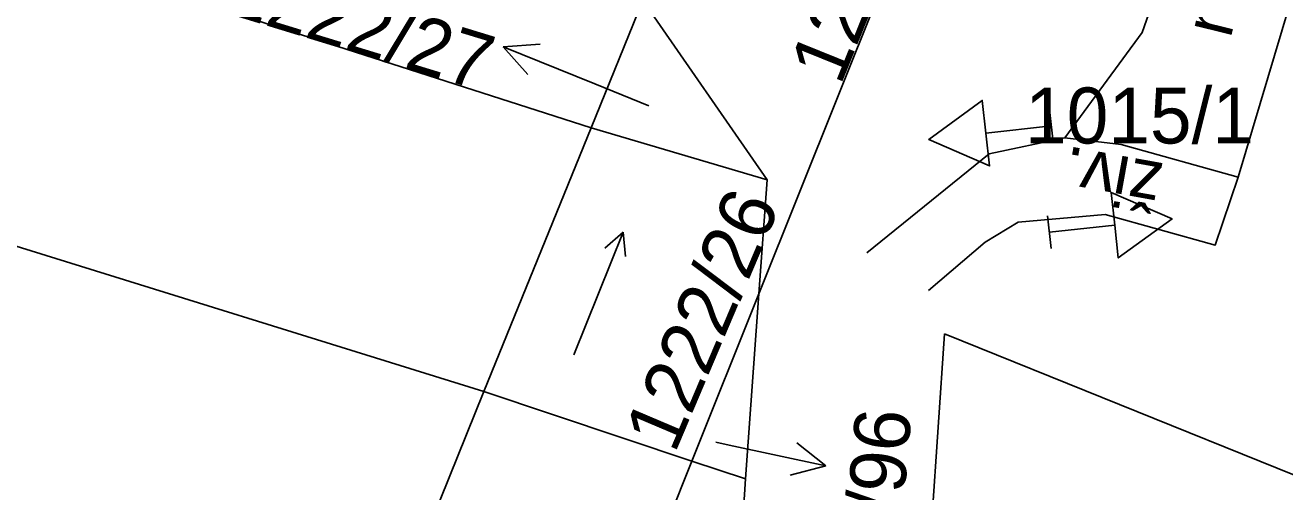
# Model space of a CAD drawing. Extents: x -779302 to -774398, y -1144902 to -1142831.
# Drawn here: x -776127.74 to -776089.47, y -1144254.14 to -1144239.97 of the extents above; entities that cross this region are included whole.
import ezdxf

# ---------------------------------------------------------------- set-up
doc = ezdxf.new("R2010")
doc.units = 0
for name, color, linetype in [('Hranice parcel', 7, 'Continuous'), ('Parcelní čísla', 7, 'Continuous'), ('Pop  PČ popisy', 7, 'Continuous'), ('zjednodus_g_situ-seda - Vrstva 51', 7, 'Continuous'), ('Značky kultur', 7, 'Continuous')]:
    doc.layers.add(name, color=color, linetype=linetype)

msp = doc.modelspace()

# ---------------------------------------------------------------- linework, layer by layer
at = {"layer": 'Hranice parcel'}
for p, q in [((-776098.59, -1144230.98), (-776105.45, -1144248.13)), ((-776108.97, -1144239.22), (-776110.54, -1144243.08)), ((-776105.2, -1144244.66), (-776108.97, -1144239.22)), ((-776110.54, -1144243.08), (-776113.8, -1144251.1)), ((-776105.2, -1144244.66), (-776110.54, -1144243.08)), ((-776105.45, -1144248.13), (-776105.2, -1144244.66)), ((-776105.45, -1144248.13), (-776107.48, -1144253.21)), ((-776105.45, -1144248.13), (-776105.85, -1144253.75)), ((-776100.36, -1144257.59), (-776099.81, -1144249.34)), ((-776099.81, -1144249.34), (-776089.17, -1144253.64)), ((-776113.8, -1144251.1), (-776118.46, -1144262.59)), ((-776107.48, -1144253.21), (-776113.8, -1144251.1)), ((-776107.48, -1144253.21), (-776112.06, -1144264.67)), ((-776107.48, -1144253.21), (-776105.85, -1144253.75)), ((-776105.85, -1144253.75), (-776106.75, -1144266.4))]:
    msp.add_line(p, q, dxfattribs=at)
for points in [[(-776110.54, -1144243.08), (-776159.55, -1144227.35), (-776214.73, -1144208.93), (-776283.73, -1144182.09), (-776414.91, -1144123.19), (-776432.86, -1144115.28), (-776478.51, -1144099.13), (-776510.43, -1144089.03), (-776541.53, -1144079.23), (-776582.13, -1144067.05), (-776608.45, -1144059.24)], [(-776609.22, -1144072.59), (-776549.62, -1144089.18), (-776477.02, -1144111.9), (-776421.35, -1144132.65), (-776283.48, -1144192.64), (-776246.29, -1144206.67), (-776201.94, -1144223.07), (-776173.05, -1144232.7), (-776113.8, -1144251.1)]]:
    msp.add_lwpolyline(points, dxfattribs=at)
at = {"layer": 'Pop  PČ popisy'}
for p, q in [((-776113.212, -1144240.626), (-776112.096, -1144240.537)), ((-776110.43, -1144241.75), (-776113.212, -1144240.626)), ((-776113.212, -1144240.626), (-776112.472, -1144241.465)), ((-776108.79, -1144242.42), (-776110.43, -1144241.75)), ((-776106.76, -1144252.64), (-776106.35, -1144252.73)), ((-776106.35, -1144252.73), (-776103.415, -1144253.354)), ((-776103.415, -1144253.354), (-776104.29, -1144252.656)), ((-776103.415, -1144253.354), (-776104.498, -1144253.636))]:
    msp.add_line(p, q, dxfattribs=at)
at = {"layer": 'zjednodus_g_situ-seda - Vrstva 51'}
for p, q in [((-776096.506, -1144243.521), (-776096.616, -1144242.527)), ((-776096.676, -1144245.76), (-776096.568, -1144246.754))]:
    msp.add_line(p, q, dxfattribs=at)
for points in [[(-776096.155, -1144243.391), (-776093.799, -1144240.19), (-776091.54, -1144233.756), (-776091.655, -1144231.045)], [(-776090.889, -1144244.587), (-776087.974, -1144234.836), (-776086.109, -1144233.339)], [(-776096.561, -1144243.024), (-776098.549, -1144243.246), (-776098.66, -1144242.252), (-776100.288, -1144243.44), (-776098.438, -1144244.239), (-776098.549, -1144243.246)], [(-776100.289, -1144248.031), (-776098.572, -1144246.557), (-776097.573, -1144245.947), (-776094.926, -1144245.714), (-776091.582, -1144246.647), (-776090.889, -1144244.587), (-776094.442, -1144243.588), (-776096.155, -1144243.391), (-776098.448, -1144243.876), (-776102.17, -1144246.879)], [(-776096.622, -1144246.257), (-776094.634, -1144246.042), (-776094.526, -1144247.036), (-776092.894, -1144245.854), (-776094.741, -1144245.048), (-776094.634, -1144246.042)]]:
    msp.add_lwpolyline(points, dxfattribs=at)
at = {"layer": 'Značky kultur'}
for p, q in [((-776111.073, -1144249.985), (-776109.567, -1144246.258)), ((-776109.567, -1144246.258), (-776110.124, -1144246.739)), ((-776109.567, -1144246.258), (-776109.501, -1144246.991))]:
    msp.add_line(p, q, dxfattribs=at)

# ---------------------------------------------------------------- texts
at = {"layer": 'Parcelní čísla'}
for s, rotation, p in [('1222/28', 68, (-776102.971, -1144241.828)), ('1222/27', 343, (-776121.709, -1144239.578)), ('1222/26', 67, (-776108.007, -1144253.012)), ('1015/96', 85, (-776101.522, -1144259.894))]:
    msp.add_text(s, height=1.7, rotation=rotation, dxfattribs=at).set_placement(p)
msp.add_text('1015/1', height=1.7, dxfattribs=at).set_placement((-776097.358, -1144243.56))
at = {"layer": 'zjednodus_g_situ-seda - Vrstva 51'}
for s, rotation, p in [('nezp.', 76.1794, (-776091.118, -1144240.394)), ('živ.', 169.759, (-776093.108, -1144244.17))]:
    msp.add_text(s, height=1.5, rotation=rotation, dxfattribs=at).set_placement(p)

doc.saveas('drawing.dxf')
